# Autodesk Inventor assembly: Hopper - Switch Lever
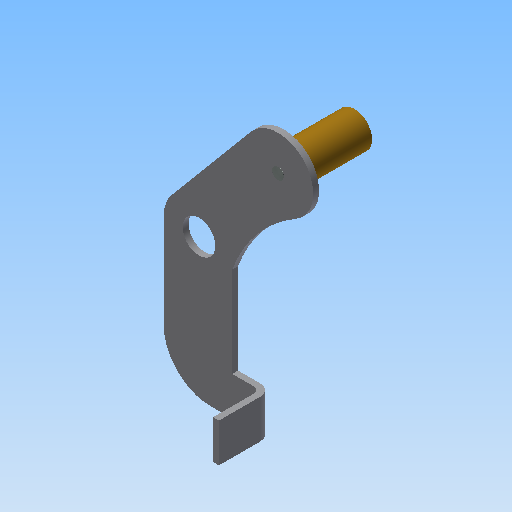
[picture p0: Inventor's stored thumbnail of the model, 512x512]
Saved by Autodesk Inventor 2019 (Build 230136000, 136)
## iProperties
Created: 2005-11
Part Number: Hopper - Switch Lever
Document SubType Name: Assembly
Designer: floress
Author: floress
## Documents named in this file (5)
- E:\Slotmachine\Slot Machine Sample\Workspace\Cabinet\Hopper\Hopper - Switch Lever.iam
- E:\Slotmachine\Slot Machine Sample\Workspace\Cabinet\Hopper\Hopper - Switch Lever.ipt
- E:\Slotmachine\Slot Machine Sample\Workspace\Cabinet\Hopper\Hopper - Roller Pin.ipt
- E:\Slotmachine\Slot Machine Sample\Workspace\Cabinet\Hopper\Hopper - Roller.ipt
- E:\Slotmachine\Slot Machine Sample\Workspace\Cabinet\Hopper\Hopper - Retaining Ring.ipt
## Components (4 placed, 4 different names)
1. Hopper - Switch Lever:1 — Flush:1, Mate:1, Mate:2
2. Hopper - Roller Pin:1 — Flush:1, Mate:1, Mate:3, Mate:4, Mate:5
3. Hopper - Roller:1 — Mate:2, Mate:3
4. Hopper - Retaining Ring:1 — Mate:4, Mate:5
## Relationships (6: Mate 5, Flush 1)
- Flush:1: Hopper - Switch Lever:1 ↔ Hopper - Roller Pin:1
- Mate:1: Hopper - Switch Lever:1 ↔ Hopper - Roller Pin:1
- Mate:2: Hopper - Switch Lever:1 ↔ Hopper - Roller:1
- Mate:3: Hopper - Roller Pin:1 ↔ Hopper - Roller:1
- Mate:4: Hopper - Roller Pin:1 ↔ Hopper - Retaining Ring:1
- Mate:5: Hopper - Roller Pin:1 ↔ Hopper - Retaining Ring:1
